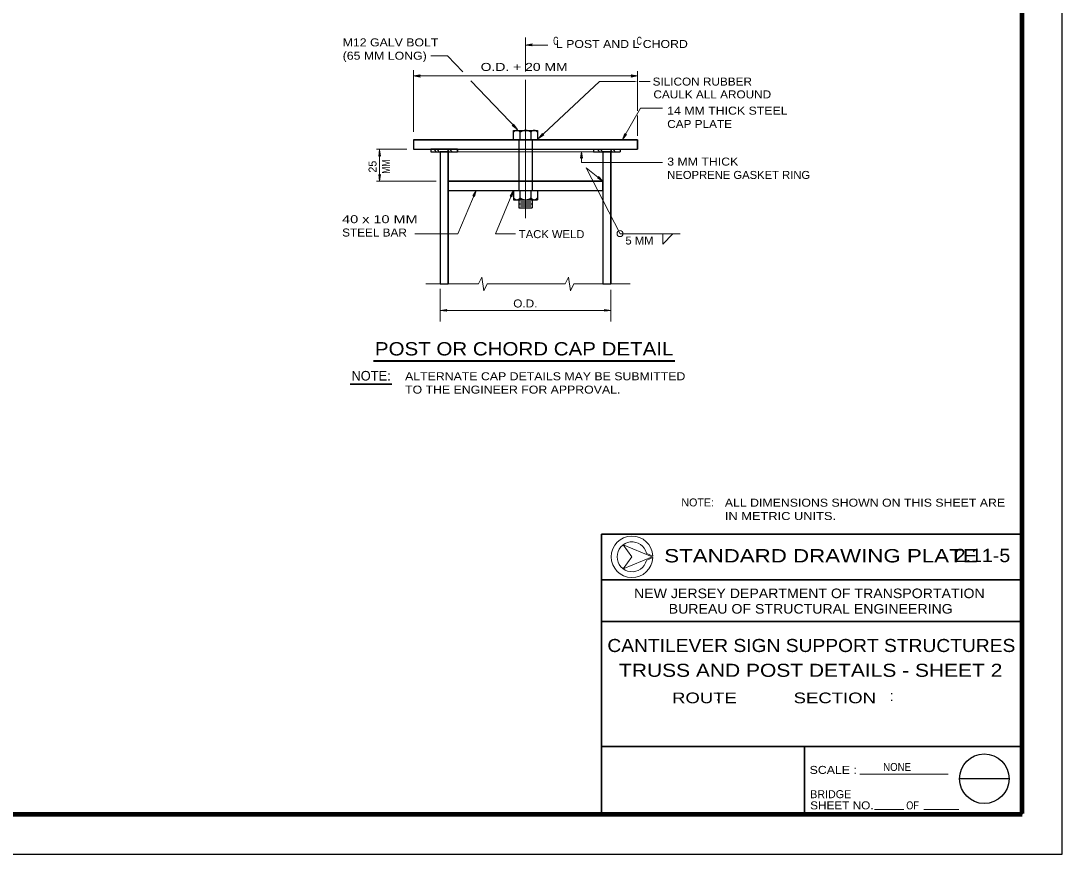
# Model space of a CAD drawing. Extents: x 312601.858 to 312602.699, y 144420.109 to 144420.704.
# Drawn here: x 312602.3083 to 312602.6988, y 144420.1095 to 144420.422 of the extents above; entities that cross this region are included whole.
import ezdxf
from ezdxf.enums import TextEntityAlignment as Align

# ---------------------------------------------------------------- set-up
doc = ezdxf.new("R2010")
doc.units = 0
doc.header["$LTSCALE"] = 0.0012
doc.linetypes.add('DOT_DASHED', pattern=[7.7, 5, -1.2, 0.3, -1.2])
doc.linetypes.add('MEDIUM_DASHED', pattern=[4.5, 3, -1.5])
for name, color, linetype, lineweight in [('1', 7, 'Continuous', 13), ('2', 7, 'Continuous', 13), ('39', 7, 'Continuous', 13)]:
    doc.layers.add(name, color=color, linetype=linetype, lineweight=lineweight)
doc.layers.add('4', color=7, linetype='Continuous')

msp = doc.modelspace()

# ---------------------------------------------------------------- hatches: boundary and pattern name
at = {"layer": '39'}
for points in [[(312602.4998, 144420.4129), (312602.5, 144420.4126), (312602.4976, 144420.4129), (312602.5, 144420.4133)], [(312602.4578, 144420.4013), (312602.458, 144420.4009), (312602.4556, 144420.4013), (312602.458, 144420.4017)], [(312602.5374, 144420.4013), (312602.5372, 144420.4017), (312602.5396, 144420.4013), (312602.5372, 144420.4009)], [(312602.493, 144420.3828), (312602.4931, 144420.3832), (312602.4945, 144420.3812), (312602.4926, 144420.3827)], [(312602.504, 144420.3793), (312602.5044, 144420.3792), (312602.5024, 144420.3778), (312602.5039, 144420.3797)], [(312602.535, 144420.3794), (312602.5354, 144420.3794), (312602.5339, 144420.3775), (312602.5348, 144420.3797)], [(312602.4428, 144420.3714), (312602.4425, 144420.3712), (312602.4428, 144420.3736), (312602.4432, 144420.3712)], [(312602.5185, 144420.3707), (312602.5182, 144420.3705), (312602.5185, 144420.3729), (312602.5189, 144420.3705)], [(312602.4428, 144420.3641), (312602.4432, 144420.3643), (312602.4428, 144420.3619), (312602.4425, 144420.3643)], [(312602.5249, 144420.3632), (312602.5249, 144420.3636), (312602.5266, 144420.3619), (312602.5245, 144420.3631)], [(312602.4782, 144420.3564), (312602.4778, 144420.3563), (312602.479, 144420.3584), (312602.4784, 144420.3561)], [(312602.4922, 144420.3563), (312602.4918, 144420.3562), (312602.493, 144420.3583), (312602.4924, 144420.356)], [(312602.4678, 144420.3134), (312602.468, 144420.3131), (312602.4656, 144420.3134), (312602.468, 144420.3138)], [(312602.5274, 144420.3134), (312602.5272, 144420.3138), (312602.5296, 144420.3134), (312602.5272, 144420.3131)]]:
    msp.add_hatch(color=256, dxfattribs=at).paths.add_polyline_path(points)

# ---------------------------------------------------------------- linework, layer by layer
at = {"layer": '1', "lineweight": 40}
msp.add_line((312602.4405, 144420.2945), (312602.5536, 144420.2945), dxfattribs=at)
at = {"layer": '1'}
msp.add_line((312602.543, 144420.2197), (312602.5453, 144420.2207), dxfattribs=at)
for points in [[(312602.5451, 144420.221), (312602.5342, 144420.2255), (312602.5451, 144420.221)], [(312602.5453, 144420.2213), (312602.543, 144420.2223), (312602.5429, 144420.2223)]]:
    msp.add_lwpolyline(points, dxfattribs=at)
for points in [[(312602.5451, 144420.221), (312602.5342, 144420.2255), (312602.5374, 144420.221), (312602.5342, 144420.2165)], [(312602.5374, 144420.221), (312602.5342, 144420.2165), (312602.5451, 144420.221), (312602.5342, 144420.2255)]]:
    msp.add_lwpolyline(points, close=True, dxfattribs=at)
for radius, start, end in [(0.0078026, 2.21392, 357.78608), (0.0056, 13.69411, 346.30589)]:
    msp.add_arc((312602.5375, 144420.221), radius, start, end, dxfattribs=at)
at = {"layer": '2'}
for p, q in [((312602.4976, 144420.4157), (312602.4976, 144420.403)), ((312602.4976, 144420.4129), (312602.5059, 144420.4129)), ((312602.4621, 144420.4088), (312602.4683, 144420.4088)), ((312602.4683, 144420.4088), (312602.474, 144420.4028)), ((312602.4556, 144420.4035), (312602.4556, 144420.3803)), ((312602.5396, 144420.4031), (312602.5396, 144420.3992)), ((312602.477, 144420.3995), (312602.4945, 144420.3812)), ((312602.5253, 144420.3992), (312602.5024, 144420.3778)), ((312602.5386, 144420.3992), (312602.5253, 144420.3992)), ((312602.539, 144420.3992), (312602.5388, 144420.3992)), ((312602.5396, 144420.3992), (312602.5396, 144420.3882)), ((312602.5443, 144420.3992), (312602.5402, 144420.3992)), ((312602.5396, 144420.3865), (312602.5396, 144420.3788)), ((312602.4931, 144420.3803), (312602.4931, 144420.3809)), ((312602.4417, 144420.3739), (312602.4531, 144420.3739)), ((312602.4637, 144420.3733), (312602.4631, 144420.3739)), ((312602.4648, 144420.3733), (312602.4642, 144420.3739)), ((312602.4685, 144420.3733), (312602.4679, 144420.3739)), ((312602.4696, 144420.3733), (312602.469, 144420.3739)), ((312602.5249, 144420.3733), (312602.5243, 144420.3739)), ((312602.526, 144420.3733), (312602.5254, 144420.3739)), ((312602.5297, 144420.3733), (312602.5291, 144420.3739)), ((312602.5308, 144420.3733), (312602.5302, 144420.3739)), ((312602.4428, 144420.3736), (312602.4428, 144420.3619)), ((312602.4641, 144420.3729), (312602.4637, 144420.3733)), ((312602.4652, 144420.3729), (312602.4648, 144420.3733)), ((312602.4689, 144420.3729), (312602.4685, 144420.3733)), ((312602.47, 144420.3729), (312602.4696, 144420.3733)), ((312602.4721, 144420.3729), (312602.5231, 144420.3729)), ((312602.5185, 144420.3689), (312602.5185, 144420.3729)), ((312602.5253, 144420.3729), (312602.5249, 144420.3733)), ((312602.5264, 144420.3729), (312602.526, 144420.3733)), ((312602.5301, 144420.3729), (312602.5297, 144420.3733)), ((312602.5312, 144420.3729), (312602.5308, 144420.3733)), ((312602.5185, 144420.3689), (312602.5489, 144420.3689)), ((312602.4417, 144420.3619), (312602.464, 144420.3619)), ((312602.493, 144420.3583), (312602.4863, 144420.3421)), ((312602.5266, 144420.3619), (312602.5202, 144420.3619)), ((312602.4938, 144420.3421), (312602.4863, 144420.3421)), ((312602.5556, 144420.3421), (312602.533, 144420.3421)), ((312602.4602, 144420.3234), (312602.4799, 144420.3234)), ((312602.4832, 144420.3234), (312602.5124, 144420.3234)), ((312602.5157, 144420.3234), (312602.5368, 144420.3234)), ((312602.4656, 144420.3215), (312602.4656, 144420.3093)), ((312602.5296, 144420.3211), (312602.5296, 144420.3093)), ((312602.4656, 144420.3134), (312602.5296, 144420.3134))]:
    msp.add_line(p, q, dxfattribs=at)
at = {"layer": '2', "linetype": 'DOT_DASHED'}
msp.add_line((312602.4976, 144420.3998), (312602.4976, 144420.348), dxfattribs=at)
at = {"layer": '2', "lineweight": 25}
for p, q in [((312602.4956, 144420.3774), (312602.4956, 144420.3809)), ((312602.4996, 144420.3809), (312602.4996, 144420.3774)), ((312602.5021, 144420.3809), (312602.5021, 144420.3774)), ((312602.4556, 144420.3774), (312602.5396, 144420.3774)), ((312602.4556, 144420.3774), (312602.4556, 144420.3739)), ((312602.4556, 144420.3739), (312602.5396, 144420.3739)), ((312602.4621, 144420.3739), (312602.4621, 144420.3729)), ((312602.4721, 144420.3739), (312602.4721, 144420.3729)), ((312602.4951, 144420.3739), (312602.4951, 144420.3619)), ((312602.5001, 144420.3739), (312602.5001, 144420.3619)), ((312602.5231, 144420.3739), (312602.5231, 144420.3729)), ((312602.5331, 144420.3739), (312602.5331, 144420.3729)), ((312602.5396, 144420.3774), (312602.5396, 144420.3739)), ((312602.4621, 144420.3729), (312602.4721, 144420.3729)), ((312602.4656, 144420.3729), (312602.4656, 144420.3234)), ((312602.4686, 144420.3729), (312602.4686, 144420.3234)), ((312602.5231, 144420.3729), (312602.5331, 144420.3729)), ((312602.5266, 144420.3729), (312602.5266, 144420.3234)), ((312602.5296, 144420.3729), (312602.5296, 144420.3234)), ((312602.4686, 144420.3619), (312602.5266, 144420.3619)), ((312602.4686, 144420.3584), (312602.5266, 144420.3584)), ((312602.4956, 144420.3549), (312602.4956, 144420.3584)), ((312602.4996, 144420.3584), (312602.4996, 144420.3549)), ((312602.5021, 144420.3584), (312602.5021, 144420.3549)), ((312602.4951, 144420.3549), (312602.4951, 144420.3519)), ((312602.5001, 144420.3549), (312602.5001, 144420.3519)), ((312602.4951, 144420.3534), (312602.5001, 144420.3534)), ((312602.4951, 144420.3519), (312602.5001, 144420.3519)), ((312602.4957, 144420.3541), (312602.4996, 144420.3541)), ((312602.4957, 144420.3526), (312602.4995, 144420.3526))]:
    msp.add_line(p, q, dxfattribs=at)
at = {"layer": '2', "linetype": 'MEDIUM_DASHED', "lineweight": 25}
for p, q in [((312602.4951, 144420.3774), (312602.4951, 144420.3739)), ((312602.5001, 144420.3774), (312602.5001, 144420.3739)), ((312602.4951, 144420.3619), (312602.4951, 144420.3584)), ((312602.5001, 144420.3619), (312602.5001, 144420.3584))]:
    msp.add_line(p, q, dxfattribs=at)
at = {"layer": '2', "lineweight": 35}
msp.add_line((312602.4474, 144420.2858), (312602.4318, 144420.2858), dxfattribs=at)
at = {"layer": '2'}
for points in [[(312602.4556, 144420.4013), (312602.4747, 144420.4013), (312602.5396, 144420.4013)], [(312602.5339, 144420.3775), (312602.5407, 144420.3892), (312602.5489, 144420.3892)], [(312602.5266, 144420.3619), (312602.5203, 144420.3668), (312602.533, 144420.3421)], [(312602.479, 144420.3584), (312602.4722, 144420.3421), (312602.4561, 144420.3421)], [(312602.549, 144420.3421), (312602.549, 144420.3383), (312602.5528, 144420.3421)], [(312602.4799, 144420.3234), (312602.4812, 144420.3259), (312602.4819, 144420.3208), (312602.4832, 144420.3234)], [(312602.5124, 144420.3234), (312602.5137, 144420.3259), (312602.5144, 144420.3208), (312602.5157, 144420.3234)]]:
    msp.add_lwpolyline(points, dxfattribs=at)
at = {"layer": '2', "lineweight": 25}
for points in [[(312602.4931, 144420.3774), (312602.4931, 144420.3809), (312602.5021, 144420.3809)], [(312602.4931, 144420.3584), (312602.4931, 144420.3549), (312602.5021, 144420.3549)]]:
    msp.add_lwpolyline(points, dxfattribs=at)
for points in [[(312602.4847, 144420.3739), (312602.5396, 144420.3739), (312602.5396, 144420.3774), (312602.4556, 144420.3774), (312602.4556, 144420.3739)], [(312602.4694, 144420.3729), (312602.4721, 144420.3729), (312602.4721, 144420.3739), (312602.4621, 144420.3739), (312602.4621, 144420.3729)], [(312602.4656, 144420.3479), (312602.4656, 144420.3234), (312602.4686, 144420.3234), (312602.4686, 144420.3729), (312602.4656, 144420.3729)], [(312602.5266, 144420.3493), (312602.5266, 144420.3234), (312602.5296, 144420.3234), (312602.5296, 144420.3729), (312602.5266, 144420.3729)], [(312602.484, 144420.3584), (312602.5266, 144420.3584), (312602.5266, 144420.3619), (312602.4686, 144420.3619), (312602.4686, 144420.3584)]]:
    msp.add_lwpolyline(points, close=True, dxfattribs=at)
at = {"layer": '2'}
msp.add_circle((312602.533, 144420.3422), 0.001118, dxfattribs=at)
at = {"layer": '2', "lineweight": 25}
for centre, radius, start, end in [((312602.49435, 144420.379436), 0.0014651, 31.44281, 148.55719), ((312602.4976, 144420.377693), 0.0032071, 51.41991, 128.58009), ((312602.50085, 144420.37945), 0.0014577, 30.96376, 149.03624), ((312602.49435, 144420.356364), 0.0014651, 211.44281, 328.55719), ((312602.4976, 144420.358107), 0.0032071, 231.41991, 308.58009), ((312602.50085, 144420.35635), 0.0014577, 210.96376, 329.03624)]:
    msp.add_arc(centre, radius, start, end, dxfattribs=at)
at = {"layer": '39', "lineweight": 25}
for p, q in [((312602.6988, 144420.1095), (312602.6988, 144420.7035)), ((312602.6789, 144420.1378), (312602.6603, 144420.1378)), ((312602.452, 144420.1245), (312602.6838, 144420.1245)), ((312601.8578, 144420.1095), (312602.6988, 144420.1095))]:
    msp.add_line(p, q, dxfattribs=at)
at = {"layer": '39', "lineweight": 158}
for p, q in [((312602.6838, 144420.1247), (312602.6838, 144420.6645)), ((312601.9088, 144420.1245), (312602.6838, 144420.1245))]:
    msp.add_line(p, q, dxfattribs=at)
at = {"layer": '39', "lineweight": 35}
for p, q in [((312602.526, 144420.1245), (312602.526, 144420.2295)), ((312602.526, 144420.2295), (312602.6838, 144420.2295)), ((312602.6838, 144420.2295), (312602.6838, 144420.1245)), ((312602.526, 144420.2124), (312602.6838, 144420.2124)), ((312602.526, 144420.1968), (312602.6838, 144420.1968)), ((312602.526, 144420.1499), (312602.6838, 144420.1499)), ((312602.6022, 144420.1248), (312602.6022, 144420.1499))]:
    msp.add_line(p, q, dxfattribs=at)
at = {"layer": '39'}
for p, q in [((312602.6022, 144420.1499), (312602.6838, 144420.1499)), ((312602.6022, 144420.1248), (312602.6022, 144420.1499)), ((312602.6022, 144420.1248), (312602.6022, 144420.1499)), ((312602.6229, 144420.1395), (312602.6561, 144420.1395)), ((312602.6284, 144420.1263), (312602.6394, 144420.1263)), ((312602.6469, 144420.1263), (312602.66, 144420.1263))]:
    msp.add_line(p, q, dxfattribs=at)
for points in [[(312602.4998, 144420.4129), (312602.5, 144420.4126), (312602.4976, 144420.4129), (312602.5, 144420.4133)], [(312602.4578, 144420.4013), (312602.458, 144420.4009), (312602.4556, 144420.4013), (312602.458, 144420.4017)], [(312602.5374, 144420.4013), (312602.5372, 144420.4017), (312602.5396, 144420.4013), (312602.5372, 144420.4009)], [(312602.493, 144420.3828), (312602.4931, 144420.3832), (312602.4945, 144420.3812), (312602.4926, 144420.3827)], [(312602.504, 144420.3793), (312602.5044, 144420.3792), (312602.5024, 144420.3778), (312602.5039, 144420.3797)], [(312602.535, 144420.3794), (312602.5354, 144420.3794), (312602.5339, 144420.3775), (312602.5348, 144420.3797)], [(312602.4428, 144420.3714), (312602.4425, 144420.3712), (312602.4428, 144420.3736), (312602.4432, 144420.3712)], [(312602.5185, 144420.3707), (312602.5182, 144420.3705), (312602.5185, 144420.3729), (312602.5189, 144420.3705)], [(312602.4428, 144420.3641), (312602.4432, 144420.3643), (312602.4428, 144420.3619), (312602.4425, 144420.3643)], [(312602.5249, 144420.3632), (312602.5249, 144420.3636), (312602.5266, 144420.3619), (312602.5245, 144420.3631)], [(312602.4782, 144420.3564), (312602.4778, 144420.3563), (312602.479, 144420.3584), (312602.4784, 144420.3561)], [(312602.4922, 144420.3563), (312602.4918, 144420.3562), (312602.493, 144420.3583), (312602.4924, 144420.356)], [(312602.4678, 144420.3134), (312602.468, 144420.3131), (312602.4656, 144420.3134), (312602.468, 144420.3138)], [(312602.5274, 144420.3134), (312602.5272, 144420.3138), (312602.5296, 144420.3134), (312602.5272, 144420.3131)], [(312602.5451, 144420.221), (312602.5342, 144420.2255), (312602.5374, 144420.221), (312602.5342, 144420.2165)]]:
    msp.add_lwpolyline(points, close=True, dxfattribs=at)
at = {"layer": '39', "lineweight": 25}
msp.add_circle((312602.6696, 144420.1378), 0.0093005, dxfattribs=at)

# ---------------------------------------------------------------- texts
at = {"layer": '2'}
for s, width, p in [('M12 GALV BOLT', 1.15, (312602.429, 144420.4124)), ('(65 MM LONG)', 1.15, (312602.429, 144420.4074)), ('14 MM THICK STEEL', 1.15, (312602.5507, 144420.3868)), ('CAP PLATE', 1.1, (312602.5507, 144420.3818)), ('3 MM THICK', 1.15, (312602.5507, 144420.3677)), ('NEOPRENE GASKET RING', 1.05, (312602.5507, 144420.3627)), ('40 x 10 MM', 1.35, (312602.4288, 144420.3461)), ('STEEL BAR', 1.1, (312602.4288, 144420.3411)), ('ALTERNATE CAP DETAILS MAY BE SUBMITTED', 1.15, (312602.4524, 144420.2872)), ('TO THE ENGINEER FOR APPROVAL.', 1.15, (312602.4524, 144420.2822))]:
    msp.add_text(s, height=0.003, dxfattribs=dict(at, width=width)).set_placement(p)
for s, height, width, p in [('C', 0.003, 0.6, (312602.5089, 144420.413)), ('L POST AND L CHORD', 0.003, 1.15, (312602.5337, 144420.4118)), ('C', 0.003, 0.6, (312602.5402, 144420.413)), ('O.D. + 20 MM', 0.003, 1.3, (312602.49705, 144420.4032)), ('SILICON RUBBER', 0.003, 1.1, (312602.56385, 144420.3977)), ('CAULK ALL AROUND', 0.003, 1.1, (312602.5676, 144420.3929)), ('TACK WELD', 0.003, 1.05, (312602.50735, 144420.3405)), ('5 MM', 0.003, 1.05, (312602.5403, 144420.3381)), ('O.D.', 0.003, 1.1, (312602.4975, 144420.3145)), ('POST OR CHORD CAP DETAIL', 0.005, 1.15, (312602.49705, 144420.2965)), ('2.11-5', 0.005, 1.1, (312602.6689, 144420.219)), ('CANTILEVER SIGN SUPPORT STRUCTURES', 0.0049, 1.1, (312602.60475, 144420.1853)), ('TRUSS AND POST DETAILS - SHEET 2', 0.0049, 1.2, (312602.6045, 144420.176)), ('NONE', 0.003, 0.9, (312602.6369, 144420.1407))]:
    msp.add_text(s, height=height, dxfattribs=dict(at, width=width)).set_placement(p, align=Align.CENTER)
msp.add_text('25', height=0.003, rotation=90, dxfattribs=at).set_placement((312602.4417, 144420.3673), align=Align.CENTER)
at = {"layer": '2', "width": 0.8}
msp.add_text('MM', height=0.003, rotation=90, dxfattribs=at).set_placement((312602.4467, 144420.3673), align=Align.CENTER)
at = {"layer": '2'}
msp.add_text('NOTE:', height=0.0036, dxfattribs=at).set_placement((312602.43965, 144420.2871), align=Align.CENTER)
at = {"layer": '39'}
for s, height, width, p in [('STANDARD DRAWING PLATE       ', 0.005, 1.25, (312602.61645, 144420.2189)), ('NEW JERSEY DEPARTMENT OF TRANSPORTATION', 0.003599, 1.1, (312602.604, 144420.2055)), ('BUREAU OF STRUCTURAL ENGINEERING', 0.0036, 1.1, (312602.6045, 144420.1997)), ('ROUTE           SECTION', 0.004, 1.3, (312602.59075, 144420.1661)), ('SCALE :', 0.003, 1.15, (312602.61295, 144420.1396)), ('OF', 0.003, 0.85, (312602.6427, 144420.1263))]:
    msp.add_text(s, height=height, dxfattribs=dict(at, width=width)).set_placement(p, align=Align.CENTER)
for p in [(312602.569737, 144420.1671), (312602.634837, 144420.1669)]:
    msp.add_text(':', height=0.004, dxfattribs=at).set_placement(p, align=Align.CENTER)
msp.add_text('BRIDGE', height=0.003, dxfattribs=at).set_placement((312602.6043, 144420.1305))
at = {"layer": '39', "width": 1.1}
msp.add_text('SHEET NO.', height=0.003, dxfattribs=at).set_placement((312602.6043, 144420.1263))
at = {"layer": '4'}
msp.add_text('NOTE:', height=0.003, dxfattribs=at).set_placement((312602.556, 144420.2399))
for s, width, p in [('ALL DIMENSIONS SHOWN ON THIS SHEET ARE', 1.15, (312602.5723, 144420.2398)), ('IN METRIC UNITS.', 1.2, (312602.5723, 144420.2348))]:
    msp.add_text(s, height=0.003, dxfattribs=dict(at, width=width)).set_placement(p)

doc.saveas('drawing.dxf')
